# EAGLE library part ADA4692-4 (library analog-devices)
Low Power, 3.6 MHz, Low Noise, Rail-to-Rail Output, Operational Amplifiers Source: http://www.analog.com/static/imported-files/data_sheets/ADA4691-2_4692-2_4692-4.pdf
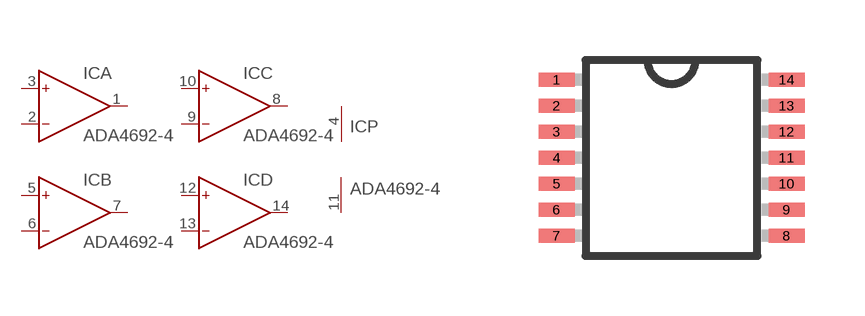
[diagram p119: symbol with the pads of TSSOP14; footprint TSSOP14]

Designator prefix IC; gates A=OP B=OP C=OP D=OP P=PWR+-

## ADA4692-4RU (MPN: ADA4692-4ARUZ; OC_FARNELL: 1827393; OC_NEWARK: 80R8154)  [TSSOP14]
1  A:OUT  out
2  A:IN-  in
3  A:IN+  in
4  P:V+  pwr
5  B:IN+  in
6  B:IN-  in
7  B:OUT  out
8  C:OUT  out
9  C:IN-  in
10  C:IN+  in
11  P:V-  pwr
12  D:IN+  in
13  D:IN-  in
14  D:OUT  out

## Footprint TSSOP14 (pad centres in mm)
14-Lead Thin Shrink Small Outline Package [TSSOP] Source: Analog Devices .. 780914713ADD8704_0.pdf
smd 0.9 x 0.35: 1 -2.875,1.95; 2 -2.875,1.3; 3 -2.875,0.65; 4 -2.875,0; 5 -2.875,-0.65; 6 -2.875,-1.3; 7 -2.875,-1.95; 8 2.875,-1.95; 9 2.875,-1.3; 10 2.875,-0.65; 11 2.875,0; 12 2.875,0.65; 13 2.875,1.3; 14 2.875,1.95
